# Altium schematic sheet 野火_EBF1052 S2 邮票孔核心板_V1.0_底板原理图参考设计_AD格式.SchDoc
size 279 x 215 mm
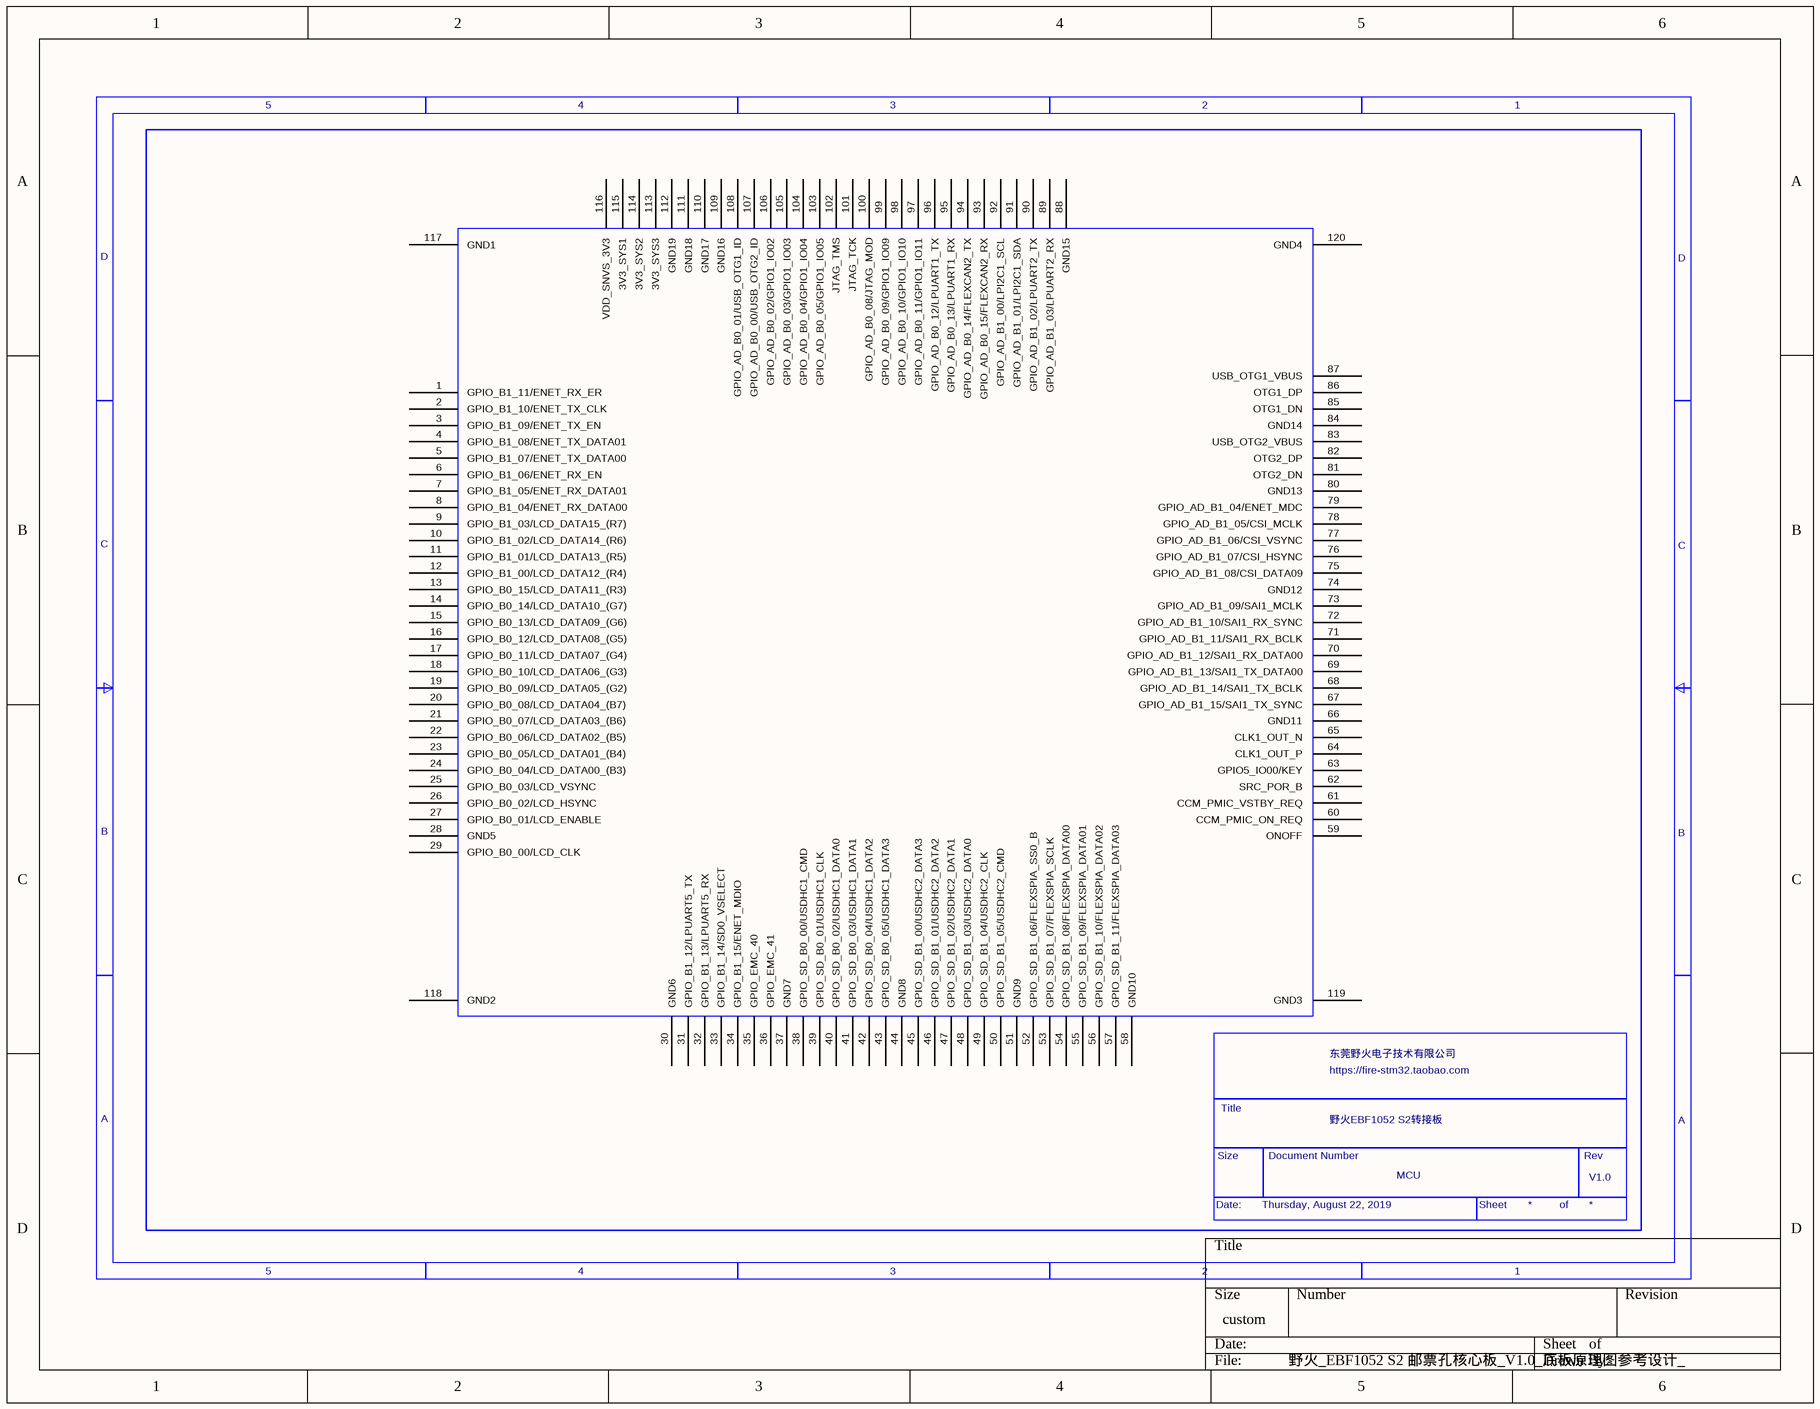
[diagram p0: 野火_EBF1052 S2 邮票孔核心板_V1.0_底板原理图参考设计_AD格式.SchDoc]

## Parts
U11  RT1052_CORE_P120_1  [RT1052_SOM_S2_116P_38X38]  (value not drawn)

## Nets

Not connected (* = marked no-connect by the designer): U11 1(GPIO_B1_11/ENET_RX_ER) 2(GPIO_B1_10/ENET_TX_CLK) 3(GPIO_B1_09/ENET_TX_EN) 4(GPIO_B1_08/ENET_TX_DATA01) 5(GPIO_B1_07/ENET_TX_DATA00) 6(GPIO_B1_06/ENET_RX_EN) 7(GPIO_B1_05/ENET_RX_DATA01) 8(GPIO_B1_04/ENET_RX_DATA00) 9(GPIO_B1_03/LCD_DATA15_(R7)) 10(GPIO_B1_02/LCD_DATA14_(R6)) 11(GPIO_B1_01/LCD_DATA13_(R5)) 12(GPIO_B1_00/LCD_DATA12_(R4)) 13(GPIO_B0_15/LCD_DATA11_(R3)) 14(GPIO_B0_14/LCD_DATA10_(G7)) 15(GPIO_B0_13/LCD_DATA09_(G6)) 16(GPIO_B0_12/LCD_DATA08_(G5)) 17(GPIO_B0_11/LCD_DATA07_(G4)) 18(GPIO_B0_10/LCD_DATA06_(G3)) 19(GPIO_B0_09/LCD_DATA05_(G2)) 20(GPIO_B0_08/LCD_DATA04_(B7)) 21(GPIO_B0_07/LCD_DATA03_(B6)) 22(GPIO_B0_06/LCD_DATA02_(B5)) 23(GPIO_B0_05/LCD_DATA01_(B4)) 24(GPIO_B0_04/LCD_DATA00_(B3)) 25(GPIO_B0_03/LCD_VSYNC) 26(GPIO_B0_02/LCD_HSYNC) 27(GPIO_B0_01/LCD_ENABLE) 28(GND5) 29(GPIO_B0_00/LCD_CLK) 30(GND6) 31(GPIO_B1_12/LPUART5_TX) 32(GPIO_B1_13/LPUART5_RX) 33(GPIO_B1_14/SD0_VSELECT) 34(GPIO_B1_15/ENET_MDIO) 35(GPIO_EMC_40) 36(GPIO_EMC_41) 37(GND7) 38(GPIO_SD_B0_00/USDHC1_CMD) 39(GPIO_SD_B0_01/USDHC1_CLK) 40(GPIO_SD_B0_02/USDHC1_DATA0) 41(GPIO_SD_B0_03/USDHC1_DATA1) 42(GPIO_SD_B0_04/USDHC1_DATA2) 43(GPIO_SD_B0_05/USDHC1_DATA3) 44(GND8) 45(GPIO_SD_B1_00/USDHC2_DATA3) 46(GPIO_SD_B1_01/USDHC2_DATA2) 47(GPIO_SD_B1_02/USDHC2_DATA1) 48(GPIO_SD_B1_03/USDHC2_DATA0) 49(GPIO_SD_B1_04/USDHC2_CLK) 50(GPIO_SD_B1_05/USDHC2_CMD) 51(GND9) 52(GPIO_SD_B1_06/FLEXSPIA_SS0_B) 53(GPIO_SD_B1_07/FLEXSPIA_SCLK) 54(GPIO_SD_B1_08/FLEXSPIA_DATA00) 55(GPIO_SD_B1_09/FLEXSPIA_DATA01) 56(GPIO_SD_B1_10/FLEXSPIA_DATA02) 57(GPIO_SD_B1_11/FLEXSPIA_DATA03) 58(GND10) 59(ONOFF) 60(CCM_PMIC_ON_REQ) 61(CCM_PMIC_VSTBY_REQ) 62(SRC_POR_B) 63(GPIO5_IO00/KEY) 64(CLK1_OUT_P) 65(CLK1_OUT_N) 66(GND11) 67(GPIO_AD_B1_15/SAI1_TX_SYNC) 68(GPIO_AD_B1_14/SAI1_TX_BCLK) 69(GPIO_AD_B1_13/SAI1_TX_DATA00) 70(GPIO_AD_B1_12/SAI1_RX_DATA00) 71(GPIO_AD_B1_11/SAI1_RX_BCLK) 72(GPIO_AD_B1_10/SAI1_RX_SYNC) 73(GPIO_AD_B1_09/SAI1_MCLK) 74(GND12) 75(GPIO_AD_B1_08/CSI_DATA09) 76(GPIO_AD_B1_07/CSI_HSYNC) 77(GPIO_AD_B1_06/CSI_VSYNC) 78(GPIO_AD_B1_05/CSI_MCLK) 79(GPIO_AD_B1_04/ENET_MDC) 80(GND13) 81(OTG2_DN) 82(OTG2_DP) 83(USB_OTG2_VBUS) 84(GND14) 85(OTG1_DN) 86(OTG1_DP) 87(USB_OTG1_VBUS) 88(GND15) 89(GPIO_AD_B1_03/LPUART2_RX) 90(GPIO_AD_B1_02/LPUART2_TX) 91(GPIO_AD_B1_01/LPI2C1_SDA) 92(GPIO_AD_B1_00/LPI2C1_SCL) 93(GPIO_AD_B0_15/FLEXCAN2_RX) 94(GPIO_AD_B0_14/FLEXCAN2_TX) 95(GPIO_AD_B0_13/LPUART1_RX) 96(GPIO_AD_B0_12/LPUART1_TX) 97(GPIO_AD_B0_11/GPIO1_IO11) 98(GPIO_AD_B0_10/GPIO1_IO10) 99(GPIO_AD_B0_09/GPIO1_IO09) 100(GPIO_AD_B0_08/JTAG_MOD) 101(JTAG_TCK) 102(JTAG_TMS) 103(GPIO_AD_B0_05/GPIO1_IO05) 104(GPIO_AD_B0_04/GPIO1_IO04) 105(GPIO_AD_B0_03/GPIO1_IO03) 106(GPIO_AD_B0_02/GPIO1_IO02) 107(GPIO_AD_B0_00/USB_OTG2_ID) 108(GPIO_AD_B0_01/USB_OTG1_ID) 109(GND16) 110(GND17) 111(GND18) 112(GND19) 113(3V3_SYS3) 114(3V3_SYS2) 115(3V3_SYS1) 116(VDD_SNVS_3V3) 117(GND1) 118(GND2) 119(GND3) 120(GND4)

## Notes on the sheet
- 5
- 4
- 3
- 2
- 1
- D
- C
- B
- Title
- (near U11) https://fire-stm32.taobao.com
- (near U11) 东莞野火电子技术有限公司
- A
- Size
- Document Number
- 野火EBF1052 S2转接板
- MCU
- Rev
- V1.0
- Date:
- Thursday, August 22, 2019
- Sheet
- of

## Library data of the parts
U11 = RT1052_CORE_P120_1: Source_Path: E:\SCH-PCB\EBF_RT002\SCH\EBF_RT002.DSN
